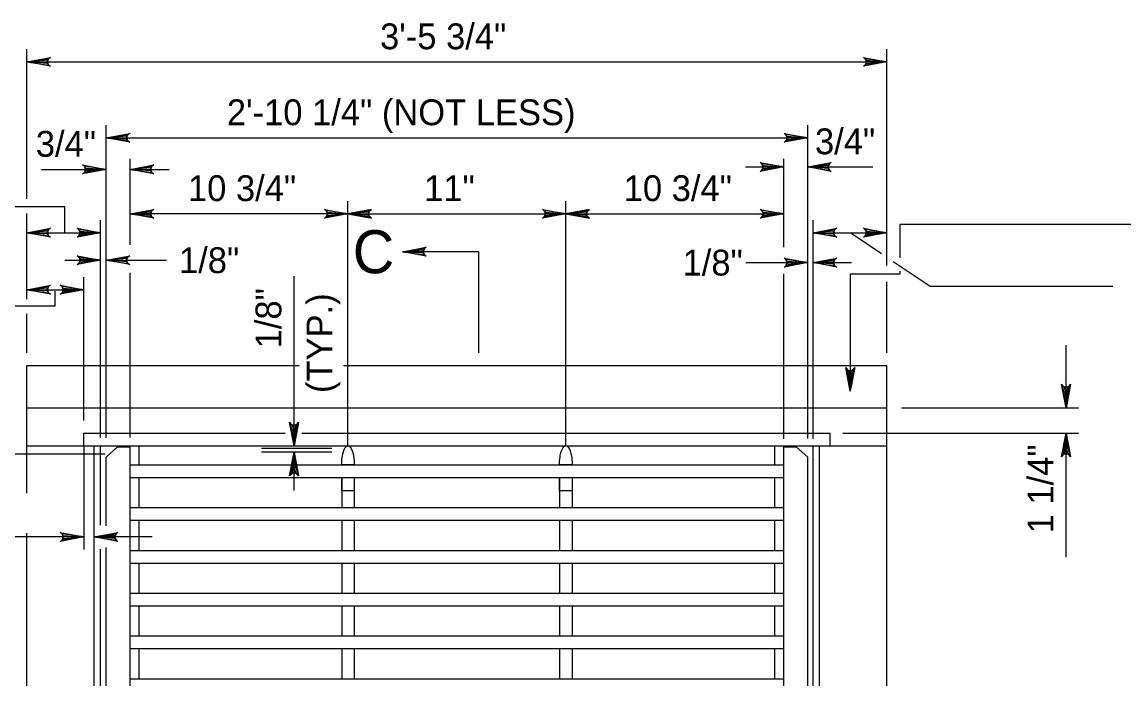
# Model space of a CAD drawing. Extents: x 0.7 to 7.67, y -7.49 to 2.47.
# Drawn here: x 3.543 to 6.105, y -3.097 to -1.57 of the extents above; entities that cross this region are included whole.
import ezdxf

# ---------------------------------------------------------------- set-up
doc = ezdxf.new("R2010")
doc.units = 0
for name, color, linetype in [('DETL-DIMS', 7, 'Continuous'), ('DETL-LINE', 7, 'Continuous'), ('DETL-NOTE', 7, 'Continuous'), ('DETL-TITL', 7, 'Continuous')]:
    doc.layers.add(name, color=color, linetype=linetype)

msp = doc.modelspace()

# ---------------------------------------------------------------- linework, layer by layer
at = {"layer": 'DETL-DIMS'}
for p, q in [((3.554, -1.9813), (3.554, -1.6335)), ((5.554, -2.1362), (5.554, -1.6335)), ((3.554, -1.6629), (5.554, -1.6629)), ((3.7383, -2.5369), (3.7383, -1.81)), ((5.3697, -2.538), (5.3697, -1.81)), ((3.7383, -1.8394), (5.3697, -1.8394)), ((3.7942, -2.0881), (3.7942, -1.8885)), ((5.3138, -2.0938), (5.3138, -1.8885)), ((3.5877, -1.9127), (3.7383, -1.9127)), ((3.7942, -1.9127), (3.8846, -1.9127)), ((5.2248, -1.907), (5.3138, -1.907)), ((5.3697, -1.907), (5.5211, -1.907)), ((4.3006, -2.5542), (4.3006, -1.9864)), ((4.8075, -2.5551), (4.8075, -1.9864)), ((3.6422, -1.9994), (3.419, -1.9994)), ((3.554, -2.2146), (3.554, -2.015)), ((3.6422, -2.0594), (3.6422, -1.9994)), ((4.3006, -2.0159), (3.7942, -2.0159)), ((4.3006, -2.0159), (4.8075, -2.0159)), ((4.8075, -2.0159), (5.3138, -2.0159)), ((3.7255, -2.5362), (3.7255, -2.0306)), ((5.3824, -2.538), (5.3824, -2.0306)), ((6.4382, -2.0409), (5.5837, -2.0409)), ((5.5837, -2.0409), (5.5837, -2.118)), ((3.554, -2.06), (3.7255, -2.06)), ((5.3824, -2.06), (5.554, -2.06)), ((5.4698, -2.06), (5.5415, -2.1083)), ((3.6426, -2.1238), (3.7255, -2.1238)), ((3.7383, -2.1238), (3.8784, -2.1238)), ((4.6042, -2.1041), (4.4278, -2.1041)), ((4.6042, -2.1041), (4.6042, -2.3394)), ((5.5685, -2.1265), (5.6546, -2.1845)), ((5.2255, -2.1294), (5.3697, -2.1294)), ((5.3824, -2.1294), (5.4717, -2.1294)), ((5.5837, -2.1491), (5.5837, -2.1561)), ((3.6863, -2.4962), (3.6863, -2.1629)), ((3.7942, -2.5362), (3.7942, -2.1528)), ((4.1752, -2.5551), (4.1752, -2.1612)), ((5.3138, -2.5387), (5.3138, -2.1556)), ((5.5837, -2.1561), (5.4686, -2.1561)), ((5.4686, -2.1561), (5.4686, -2.4283)), ((5.554, -2.3394), (5.554, -2.174)), ((3.554, -2.1923), (3.6863, -2.1923)), ((3.6194, -2.1958), (3.6194, -2.2309)), ((5.6546, -2.1845), (6.0789, -2.1845)), ((3.6194, -2.2309), (2.374, -2.2309)), ((3.554, -2.3394), (3.554, -2.2484)), ((5.9703, -2.4668), (5.9703, -2.321)), ((5.5879, -2.4668), (5.9997, -2.4668)), ((5.451, -2.5257), (5.9997, -2.5257)), ((5.9703, -2.8142), (5.9703, -2.5257)), ((3.6863, -2.5551), (3.6863, -2.7964)), ((3.7349, -2.5748), (3.0834, -2.5748)), ((4.1752, -2.6588), (4.1752, -2.5701)), ((3.6863, -2.767), (3.1719, -2.767)), ((3.8452, -2.767), (3.7108, -2.767))]:
    msp.add_line(p, q, dxfattribs=at)
for points in [[(3.554, -1.6629), (3.6088, -1.6526), (3.6046, -1.6556), (3.6024, -1.6592), (3.6018, -1.6629), (3.6024, -1.6666), (3.6046, -1.6703), (3.6088, -1.6732), (3.554, -1.6629), (3.6046, -1.6703), (3.6024, -1.6666), (3.554, -1.6629), (3.6018, -1.6629), (3.6024, -1.6592), (3.554, -1.6629), (3.6046, -1.6556)], [(5.554, -1.6629), (5.4992, -1.6732), (5.5034, -1.6703), (5.5056, -1.6666), (5.5062, -1.6629), (5.5056, -1.6592), (5.5034, -1.6556), (5.4992, -1.6526), (5.554, -1.6629), (5.5034, -1.6556), (5.5056, -1.6592), (5.554, -1.6629), (5.5062, -1.6629), (5.5056, -1.6666), (5.554, -1.6629), (5.5034, -1.6703)], [(3.7383, -1.8394), (3.7931, -1.8291), (3.7889, -1.832), (3.7867, -1.8357), (3.7861, -1.8394), (3.7867, -1.8431), (3.7889, -1.8467), (3.7931, -1.8497), (3.7383, -1.8394), (3.7889, -1.8467), (3.7867, -1.8431), (3.7383, -1.8394), (3.7861, -1.8394), (3.7867, -1.8357), (3.7383, -1.8394), (3.7889, -1.832)], [(5.3697, -1.8394), (5.3148, -1.8497), (5.3191, -1.8467), (5.3212, -1.8431), (5.3219, -1.8394), (5.3212, -1.8357), (5.3191, -1.832), (5.3148, -1.8291), (5.3697, -1.8394), (5.3191, -1.832), (5.3212, -1.8357), (5.3697, -1.8394), (5.3219, -1.8394), (5.3212, -1.8431), (5.3697, -1.8394), (5.3191, -1.8467)], [(3.7383, -1.9127), (3.6835, -1.9229), (3.6877, -1.92), (3.6899, -1.9163), (3.6905, -1.9127), (3.6899, -1.909), (3.6877, -1.9053), (3.6835, -1.9024), (3.7383, -1.9127), (3.6877, -1.9053), (3.6899, -1.909), (3.7383, -1.9127), (3.6905, -1.9127), (3.6899, -1.9163), (3.7383, -1.9127), (3.6877, -1.92)], [(3.7942, -1.9127), (3.849, -1.9024), (3.8448, -1.9053), (3.8426, -1.909), (3.842, -1.9127), (3.8426, -1.9163), (3.8448, -1.92), (3.849, -1.9229), (3.7942, -1.9127), (3.8448, -1.92), (3.8426, -1.9163), (3.7942, -1.9127), (3.842, -1.9127), (3.8426, -1.909), (3.7942, -1.9127), (3.8448, -1.9053)], [(5.3138, -1.907), (5.259, -1.9173), (5.2632, -1.9144), (5.2654, -1.9107), (5.266, -1.907), (5.2654, -1.9034), (5.2632, -1.8997), (5.259, -1.8968), (5.3138, -1.907), (5.2632, -1.8997), (5.2654, -1.9034), (5.3138, -1.907), (5.266, -1.907), (5.2654, -1.9107), (5.3138, -1.907), (5.2632, -1.9144)], [(5.3697, -1.907), (5.4245, -1.8968), (5.4203, -1.8997), (5.4181, -1.9034), (5.4175, -1.907), (5.4181, -1.9107), (5.4203, -1.9144), (5.4245, -1.9173), (5.3697, -1.907), (5.4203, -1.9144), (5.4181, -1.9107), (5.3697, -1.907), (5.4175, -1.907), (5.4181, -1.9034), (5.3697, -1.907), (5.4203, -1.8997)], [(3.7942, -2.0159), (3.849, -2.0056), (3.8448, -2.0085), (3.8426, -2.0122), (3.842, -2.0159), (3.8426, -2.0195), (3.8448, -2.0232), (3.849, -2.0261), (3.7942, -2.0159), (3.8448, -2.0232), (3.8426, -2.0195), (3.7942, -2.0159), (3.842, -2.0159), (3.8426, -2.0122), (3.7942, -2.0159), (3.8448, -2.0085)], [(4.3006, -2.0159), (4.2458, -2.0261), (4.25, -2.0232), (4.2522, -2.0195), (4.2528, -2.0159), (4.2522, -2.0122), (4.25, -2.0085), (4.2458, -2.0056), (4.3006, -2.0159), (4.25, -2.0085), (4.2522, -2.0122), (4.3006, -2.0159), (4.2528, -2.0159), (4.2522, -2.0195), (4.3006, -2.0159), (4.25, -2.0232)], [(4.3006, -2.0159), (4.3554, -2.0261), (4.3512, -2.0232), (4.349, -2.0195), (4.3484, -2.0159), (4.349, -2.0122), (4.3512, -2.0085), (4.3554, -2.0056), (4.3006, -2.0159), (4.3512, -2.0085), (4.349, -2.0122), (4.3006, -2.0159), (4.3484, -2.0159), (4.349, -2.0195), (4.3006, -2.0159), (4.3512, -2.0232)], [(4.8075, -2.0159), (4.7527, -2.0261), (4.7569, -2.0232), (4.7591, -2.0195), (4.7597, -2.0159), (4.7591, -2.0122), (4.7569, -2.0085), (4.7527, -2.0056), (4.8075, -2.0159), (4.7569, -2.0085), (4.7591, -2.0122), (4.8075, -2.0159), (4.7597, -2.0159), (4.7591, -2.0195), (4.8075, -2.0159), (4.7569, -2.0232)], [(4.8075, -2.0159), (4.8624, -2.0261), (4.8581, -2.0232), (4.856, -2.0195), (4.8553, -2.0159), (4.856, -2.0122), (4.8581, -2.0085), (4.8624, -2.0056), (4.8075, -2.0159), (4.8581, -2.0085), (4.856, -2.0122), (4.8075, -2.0159), (4.8553, -2.0159), (4.856, -2.0195), (4.8075, -2.0159), (4.8581, -2.0232)], [(5.3138, -2.0159), (5.259, -2.0261), (5.2632, -2.0232), (5.2654, -2.0195), (5.266, -2.0159), (5.2654, -2.0122), (5.2632, -2.0085), (5.259, -2.0056), (5.3138, -2.0159), (5.2632, -2.0085), (5.2654, -2.0122), (5.3138, -2.0159), (5.266, -2.0159), (5.2654, -2.0195), (5.3138, -2.0159), (5.2632, -2.0232)], [(3.554, -2.06), (3.6088, -2.0497), (3.6046, -2.0526), (3.6024, -2.0563), (3.6018, -2.06), (3.6024, -2.0636), (3.6046, -2.0673), (3.6088, -2.0703), (3.554, -2.06), (3.6046, -2.0673), (3.6024, -2.0636), (3.554, -2.06), (3.6018, -2.06), (3.6024, -2.0563), (3.554, -2.06), (3.6046, -2.0526)], [(3.7255, -2.06), (3.6707, -2.0703), (3.6749, -2.0673), (3.6771, -2.0636), (3.6778, -2.06), (3.6771, -2.0563), (3.6749, -2.0526), (3.6707, -2.0497), (3.7255, -2.06), (3.6749, -2.0526), (3.6771, -2.0563), (3.7255, -2.06), (3.6778, -2.06), (3.6771, -2.0636), (3.7255, -2.06), (3.6749, -2.0673)], [(5.3824, -2.06), (5.4372, -2.0497), (5.433, -2.0526), (5.4308, -2.0563), (5.4302, -2.06), (5.4308, -2.0636), (5.433, -2.0673), (5.4372, -2.0703), (5.3824, -2.06), (5.433, -2.0673), (5.4308, -2.0636), (5.3824, -2.06), (5.4302, -2.06), (5.4308, -2.0563), (5.3824, -2.06), (5.433, -2.0526)], [(5.554, -2.06), (5.4992, -2.0703), (5.5034, -2.0673), (5.5056, -2.0636), (5.5062, -2.06), (5.5056, -2.0563), (5.5034, -2.0526), (5.4992, -2.0497), (5.554, -2.06), (5.5034, -2.0526), (5.5056, -2.0563), (5.554, -2.06), (5.5062, -2.06), (5.5056, -2.0636), (5.554, -2.06), (5.5034, -2.0673)], [(4.4278, -2.1041), (4.4826, -2.0938), (4.4784, -2.0967), (4.4762, -2.1004), (4.4756, -2.1041), (4.4762, -2.1078), (4.4784, -2.1114), (4.4826, -2.1144), (4.4278, -2.1041), (4.4784, -2.1114), (4.4762, -2.1078), (4.4278, -2.1041), (4.4756, -2.1041), (4.4762, -2.1004), (4.4278, -2.1041), (4.4784, -2.0967)], [(3.7255, -2.1238), (3.6707, -2.134), (3.6749, -2.1311), (3.6771, -2.1274), (3.6778, -2.1238), (3.6771, -2.1201), (3.6749, -2.1164), (3.6707, -2.1135), (3.7255, -2.1238), (3.6749, -2.1164), (3.6771, -2.1201), (3.7255, -2.1238), (3.6778, -2.1238), (3.6771, -2.1274), (3.7255, -2.1238), (3.6749, -2.1311)], [(3.7383, -2.1238), (3.7931, -2.1135), (3.7889, -2.1164), (3.7867, -2.1201), (3.7861, -2.1238), (3.7867, -2.1274), (3.7889, -2.1311), (3.7931, -2.134), (3.7383, -2.1238), (3.7889, -2.1311), (3.7867, -2.1274), (3.7383, -2.1238), (3.7861, -2.1238), (3.7867, -2.1201), (3.7383, -2.1238), (3.7889, -2.1164)], [(5.3697, -2.1294), (5.3148, -2.1397), (5.3191, -2.1367), (5.3212, -2.1331), (5.3219, -2.1294), (5.3212, -2.1257), (5.3191, -2.122), (5.3148, -2.1191), (5.3697, -2.1294), (5.3191, -2.122), (5.3212, -2.1257), (5.3697, -2.1294), (5.3219, -2.1294), (5.3212, -2.1331), (5.3697, -2.1294), (5.3191, -2.1367)], [(5.3824, -2.1294), (5.4372, -2.1191), (5.433, -2.122), (5.4308, -2.1257), (5.4302, -2.1294), (5.4308, -2.1331), (5.433, -2.1367), (5.4372, -2.1397), (5.3824, -2.1294), (5.433, -2.1367), (5.4308, -2.1331), (5.3824, -2.1294), (5.4302, -2.1294), (5.4308, -2.1257), (5.3824, -2.1294), (5.433, -2.122)], [(3.554, -2.1923), (3.6088, -2.182), (3.6046, -2.185), (3.6024, -2.1886), (3.6018, -2.1923), (3.6024, -2.196), (3.6046, -2.1997), (3.6088, -2.2026), (3.554, -2.1923), (3.6046, -2.1997), (3.6024, -2.196), (3.554, -2.1923), (3.6018, -2.1923), (3.6024, -2.1886), (3.554, -2.1923), (3.6046, -2.185)], [(3.6863, -2.1923), (3.6315, -2.2026), (3.6357, -2.1997), (3.6379, -2.196), (3.6385, -2.1923), (3.6379, -2.1886), (3.6357, -2.185), (3.6315, -2.182), (3.6863, -2.1923), (3.6357, -2.185), (3.6379, -2.1886), (3.6863, -2.1923), (3.6385, -2.1923), (3.6379, -2.196), (3.6863, -2.1923), (3.6357, -2.1997)], [(5.4686, -2.4283), (5.4583, -2.3734), (5.4613, -2.3777), (5.4649, -2.3798), (5.4686, -2.3805), (5.4723, -2.3798), (5.476, -2.3777), (5.4789, -2.3734), (5.4686, -2.4283), (5.476, -2.3777), (5.4723, -2.3798), (5.4686, -2.4283), (5.4686, -2.3805), (5.4649, -2.3798), (5.4686, -2.4283), (5.4613, -2.3777)], [(5.9703, -2.4668), (5.96, -2.412), (5.9629, -2.4162), (5.9666, -2.4184), (5.9703, -2.419), (5.9739, -2.4184), (5.9776, -2.4162), (5.9805, -2.412), (5.9703, -2.4668), (5.9776, -2.4162), (5.9739, -2.4184), (5.9703, -2.4668), (5.9703, -2.419), (5.9666, -2.4184), (5.9703, -2.4668), (5.9629, -2.4162)], [(4.1752, -2.5551), (4.1649, -2.5002), (4.1678, -2.5045), (4.1715, -2.5066), (4.1752, -2.5073), (4.1788, -2.5066), (4.1825, -2.5045), (4.1854, -2.5002), (4.1752, -2.5551), (4.1825, -2.5045), (4.1788, -2.5066), (4.1752, -2.5551), (4.1752, -2.5073), (4.1715, -2.5066), (4.1752, -2.5551), (4.1678, -2.5045)], [(5.9703, -2.5257), (5.9805, -2.5805), (5.9776, -2.5763), (5.9739, -2.5741), (5.9703, -2.5735), (5.9666, -2.5741), (5.9629, -2.5763), (5.96, -2.5805), (5.9703, -2.5257), (5.9629, -2.5763), (5.9666, -2.5741), (5.9703, -2.5257), (5.9703, -2.5735), (5.9739, -2.5741), (5.9703, -2.5257), (5.9776, -2.5763)], [(4.1752, -2.5701), (4.1854, -2.6249), (4.1825, -2.6207), (4.1788, -2.6185), (4.1752, -2.6179), (4.1715, -2.6185), (4.1678, -2.6207), (4.1649, -2.6249), (4.1752, -2.5701), (4.1678, -2.6207), (4.1715, -2.6185), (4.1752, -2.5701), (4.1752, -2.6179), (4.1788, -2.6185), (4.1752, -2.5701), (4.1825, -2.6207)], [(3.6863, -2.767), (3.6315, -2.7772), (3.6357, -2.7743), (3.6379, -2.7706), (3.6385, -2.767), (3.6379, -2.7633), (3.6357, -2.7596), (3.6315, -2.7567), (3.6863, -2.767), (3.6357, -2.7596), (3.6379, -2.7633), (3.6863, -2.767), (3.6385, -2.767), (3.6379, -2.7706), (3.6863, -2.767), (3.6357, -2.7743)], [(3.7108, -2.767), (3.7657, -2.7567), (3.7614, -2.7596), (3.7593, -2.7633), (3.7586, -2.767), (3.7593, -2.7706), (3.7614, -2.7743), (3.7657, -2.7772), (3.7108, -2.767), (3.7614, -2.7743), (3.7593, -2.7706), (3.7108, -2.767), (3.7586, -2.767), (3.7593, -2.7633), (3.7108, -2.767), (3.7614, -2.7596)]]:
    msp.add_lwpolyline(points, dxfattribs=at)
at = {"layer": 'DETL-LINE'}
for p, q in [((3.554, -2.3688), (4.1868, -2.3688)), ((3.554, -2.6654), (3.554, -2.3688)), ((4.2903, -2.3688), (5.554, -2.3688)), ((5.554, -4.2511), (5.554, -2.3688)), ((3.554, -2.4668), (5.554, -2.4668)), ((3.6863, -2.5551), (3.6863, -2.5257)), ((3.6863, -2.5257), (4.1543, -2.5257)), ((4.1936, -2.5257), (5.4216, -2.5257)), ((5.4216, -2.5551), (5.4216, -2.5257)), ((3.554, -2.5551), (5.554, -2.5551)), ((3.7108, -4.0649), (3.7108, -2.5551)), ((3.7255, -2.7392), (3.7255, -2.5551)), ((3.7383, -2.5818), (3.7648, -2.5576)), ((3.7648, -2.5576), (3.7942, -2.5576)), ((3.7942, -4.0649), (3.7942, -2.5551)), ((3.8148, -2.5992), (3.8148, -2.5551)), ((4.263, -2.5617), (4.0994, -2.5617)), ((5.2932, -2.5992), (5.2932, -2.5551)), ((5.3138, -4.0649), (5.3138, -2.5551)), ((5.3138, -2.5577), (5.3432, -2.5577)), ((5.3697, -2.5818), (5.3432, -2.5577)), ((5.3824, -4.0649), (5.3824, -2.5551)), ((5.3971, -4.0649), (5.3971, -2.5551)), ((3.7383, -2.7413), (3.7383, -2.5818)), ((4.263, -2.5701), (4.0994, -2.5701)), ((5.3697, -4.0381), (5.3697, -2.5818)), ((3.7942, -2.5992), (5.3138, -2.5992)), ((3.7942, -2.6286), (5.3138, -2.6286)), ((3.8148, -2.6986), (3.8148, -2.6286)), ((4.286, -2.6286), (4.286, -2.6986)), ((4.3154, -2.6286), (4.3154, -2.6986)), ((4.7925, -2.6286), (4.7925, -2.6986)), ((4.822, -2.6286), (4.822, -2.6986)), ((5.2932, -2.6986), (5.2932, -2.6286)), ((3.7942, -2.6986), (5.3138, -2.6986)), ((3.7942, -2.728), (5.3138, -2.728)), ((3.8148, -2.7981), (3.8148, -2.728)), ((4.286, -2.728), (4.286, -2.7981)), ((4.3154, -2.728), (4.3154, -2.7981)), ((4.7925, -2.728), (4.7925, -2.7981)), ((4.822, -2.728), (4.822, -2.7981)), ((5.2932, -2.7981), (5.2932, -2.728)), ((3.554, -4.2511), (3.554, -2.7585)), ((3.7383, -4.0381), (3.7383, -2.7912)), ((3.7255, -4.0649), (3.7255, -2.7953)), ((3.7942, -2.7981), (5.3138, -2.7981)), ((3.7942, -2.8275), (5.3138, -2.8275)), ((3.8148, -2.8975), (3.8148, -2.8275)), ((4.286, -2.8275), (4.286, -2.8975)), ((4.3154, -2.8275), (4.3154, -2.8975)), ((4.7925, -2.8275), (4.7925, -2.8975)), ((4.822, -2.8275), (4.822, -2.8975)), ((5.2932, -2.8975), (5.2932, -2.8275)), ((3.7942, -2.8975), (5.3138, -2.8975)), ((3.7942, -2.9269), (5.3138, -2.9269)), ((3.8148, -2.9969), (3.8148, -2.9269)), ((4.286, -2.9269), (4.286, -2.9969)), ((4.3154, -2.9269), (4.3154, -2.9969)), ((4.7925, -2.9269), (4.7925, -2.9969)), ((4.822, -2.9269), (4.822, -2.9969)), ((5.2932, -2.9969), (5.2932, -2.9269)), ((3.7942, -2.9969), (5.3138, -2.9969)), ((3.7942, -3.0264), (5.3138, -3.0264)), ((3.8148, -3.0964), (3.8148, -3.0264)), ((4.286, -3.0264), (4.286, -3.0964)), ((4.3154, -3.0264), (4.3154, -3.0964)), ((4.7925, -3.0264), (4.7925, -3.0964)), ((4.822, -3.0264), (4.822, -3.0964)), ((5.2932, -3.0964), (5.2932, -3.0264)), ((3.7942, -3.0964), (5.3138, -3.0964))]:
    msp.add_line(p, q, dxfattribs=at)
for points in [[(4.286, -2.5992), (4.2863, -2.5906), (4.2867, -2.5859), (4.2872, -2.5823), (4.2876, -2.5784), (4.2886, -2.5736), (4.2899, -2.5686), (4.2919, -2.5638), (4.2942, -2.5592), (4.2964, -2.5568), (4.2986, -2.5553), (4.3008, -2.555), (4.3024, -2.5551), (4.3038, -2.5558), (4.3053, -2.5572), (4.3067, -2.5588), (4.3083, -2.5615), (4.3106, -2.5666), (4.3126, -2.5727), (4.3136, -2.5786), (4.3144, -2.5837), (4.315, -2.5882), (4.3153, -2.5924), (4.3154, -2.5992)], [(4.7925, -2.5992), (4.7928, -2.5906), (4.7933, -2.5859), (4.7937, -2.5823), (4.7942, -2.5784), (4.7951, -2.5736), (4.7964, -2.5686), (4.7984, -2.5638), (4.8008, -2.5592), (4.8029, -2.5568), (4.8051, -2.5553), (4.8073, -2.555), (4.809, -2.5551), (4.8103, -2.5558), (4.8119, -2.5572), (4.8132, -2.5588), (4.8149, -2.5615), (4.8172, -2.5666), (4.8191, -2.5727), (4.8202, -2.5786), (4.821, -2.5837), (4.8215, -2.5882), (4.8219, -2.5924), (4.822, -2.5992)], [(4.2863, -2.6286), (4.3154, -2.6286), (4.3154, -2.6596), (4.2863, -2.6596)], [(4.7929, -2.6286), (4.822, -2.6286), (4.822, -2.6596), (4.7929, -2.6596)]]:
    msp.add_lwpolyline(points, close=True, dxfattribs=at)

# ---------------------------------------------------------------- texts
at = {"layer": 'DETL-NOTE'}
for s, p in [('3\'-5 3/4"', (4.3752, -1.6335)), ('2\'-10 1/4" (NOT LESS)', (4.019, -1.81)), ('3/4"', (5.3866, -1.8776)), ('3/4"', (3.5748, -1.8833)), ('10 3/4"', (3.9286, -1.9864)), ('11"', (4.4777, -1.9864)), ('10 3/4"', (4.9419, -1.9864)), ('1/8"', (3.9078, -2.1538)), ('1/8"', (5.0787, -2.1594))]:
    msp.add_text(s, height=0.06, dxfattribs=at).set_placement(p)
for s, p in [('1/8"', (4.1457, -2.3287)), ('(TYP.)', (4.2646, -2.4325)), ('1 1/4"', (5.9409, -2.7587))]:
    msp.add_text(s, height=0.06, rotation=90, dxfattribs=at).set_placement(p)
at = {"layer": 'DETL-TITL'}
msp.add_text('C', height=0.1, dxfattribs=at).set_placement((4.3118, -2.1541))

doc.saveas('drawing.dxf')
